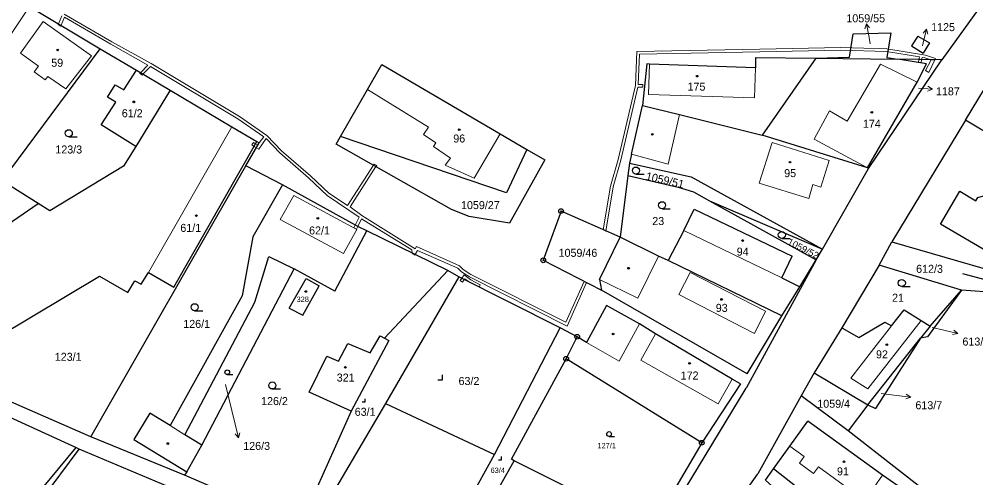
# Model space of a CAD drawing. Extents: x -694609 to -690140, y -1033292 to -1029794.
# Drawn here: x -692506.4 to -692303.2, y -1031568.1 to -1031470.7 of the extents above; entities that cross this region are included whole.
import ezdxf
from ezdxf.enums import TextEntityAlignment as Align

# ---------------------------------------------------------------- set-up
doc = ezdxf.new("R2010")
doc.units = 0
doc.header["$LTSCALE"] = 0.68
for name, color, linetype, lineweight in [('1', 7, 'Continuous', 25), ('13', 7, 'Continuous', 13), ('3', 7, 'Continuous', 25), ('4', 7, 'Continuous', 13), ('5', 7, 'Continuous', 25), ('7', 7, 'Continuous', 13), ('8', 7, 'Continuous', 25)]:
    doc.layers.add(name, color=color, linetype=linetype, lineweight=lineweight)
doc.layers.add('2', color=7, linetype='Continuous')

msp = doc.modelspace()

# ---------------------------------------------------------------- linework, layer by layer
at = {"layer": '1'}
for p, q in [((-692296.63, -1031460.11), (-692310.42, -1031479.32)), ((-692504.17, -1031467.97), (-692489.17, -1031476.96)), ((-692330.05, -1031478.76), (-692329.26, -1031473.82)), ((-692329.26, -1031473.82), (-692321.23, -1031473.6)), ((-692321.23, -1031473.6), (-692322.07, -1031478.82)), ((-692315.53, -1031474.28), (-692316.87, -1031476.38)), ((-692315.53, -1031474.28), (-692313.04, -1031475.74)), ((-692305.4, -1031492.16), (-692294.9, -1031474.76)), ((-692509.98, -1031505.02), (-692489.17, -1031476.96)), ((-692489.17, -1031476.96), (-692481.44, -1031481.54)), ((-692316.87, -1031476.38), (-692314.35, -1031477.91)), ((-692313.04, -1031475.74), (-692314.35, -1031477.91)), ((-692349.96, -1031478.82), (-692349.98, -1031481.02)), ((-692337.17, -1031478.95), (-692330.05, -1031478.76)), ((-692337.17, -1031478.95), (-692319.74, -1031479.19)), ((-692322.07, -1031478.82), (-692319.74, -1031479.19)), ((-692310.42, -1031479.32), (-692319.74, -1031479.19)), ((-692313.7, -1031480.16), (-692319.74, -1031479.19)), ((-692432.37, -1031485.64), (-692429.33, -1031480.34)), ((-692429.33, -1031480.34), (-692404.21, -1031495.03)), ((-692373.05, -1031480.2), (-692374, -1031489.01)), ((-692372.47, -1031480.22), (-692373.05, -1031480.2)), ((-692349.98, -1031481.02), (-692372.47, -1031480.22)), ((-692325.97, -1031502.39), (-692310.42, -1031479.32)), ((-692484.12, -1031485.72), (-692481.44, -1031481.54)), ((-692481.44, -1031481.54), (-692474.29, -1031485.77)), ((-692487.59, -1031487.25), (-692485.93, -1031484.64)), ((-692485.93, -1031484.64), (-692484.12, -1031485.72)), ((-692485.8, -1031488.33), (-692487.59, -1031487.25)), ((-692474.29, -1031485.77), (-692481.58, -1031497.74)), ((-692474.29, -1031485.77), (-692461.2, -1031493.52)), ((-692438.08, -1031495.6), (-692432.37, -1031485.64)), ((-692488.9, -1031493.15), (-692485.8, -1031488.33)), ((-692376.3, -1031499.39), (-692374, -1031489.01)), ((-692374, -1031489.01), (-692366.1, -1031490.96)), ((-692366.1, -1031490.96), (-692348.54, -1031495.3)), ((-692481.58, -1031497.74), (-692488.9, -1031493.15)), ((-692305.4, -1031492.16), (-692321.02, -1031518)), ((-692243.47, -1031529.16), (-692305.4, -1031492.16)), ((-692461.2, -1031493.52), (-692455.86, -1031496.68)), ((-692404.21, -1031495.03), (-692398.52, -1031498.35)), ((-692326.22, -1031502.28), (-692348.54, -1031495.3)), ((-692473.53, -1031527.58), (-692455.86, -1031496.68)), ((-692458.24, -1031501.84), (-692455.37, -1031496.97)), ((-692455.86, -1031496.68), (-692455.37, -1031496.97)), ((-692439.01, -1031497.22), (-692438.08, -1031495.6)), ((-692414.51, -1031511.12), (-692439.01, -1031497.22)), ((-692402.85, -1031507.59), (-692438.08, -1031495.6)), ((-692481.58, -1031497.74), (-692484.21, -1031501.91)), ((-692398.52, -1031498.35), (-692402.85, -1031507.59)), ((-692398.52, -1031498.35), (-692394.71, -1031500.58)), ((-692376.3, -1031499.39), (-692376.72, -1031501.27)), ((-692394.71, -1031500.58), (-692402.2, -1031514.03)), ((-692376.72, -1031501.27), (-692377.08, -1031503.89)), ((-692376.72, -1031501.27), (-692363.67, -1031504.14)), ((-692484.21, -1031501.91), (-692499.85, -1031511.41)), ((-692491.14, -1031559.38), (-692458.24, -1031501.84)), ((-692450.42, -1031505.9), (-692458.24, -1031501.84)), ((-692335.75, -1031519.57), (-692325.97, -1031502.39)), ((-692325.97, -1031502.39), (-692326.22, -1031502.28)), ((-692502.29, -1031509.87), (-692509.98, -1031505.02)), ((-692377.08, -1031503.89), (-692378.73, -1031517.02)), ((-692377.08, -1031503.89), (-692366.42, -1031506.38)), ((-692363.67, -1031504.14), (-692335.75, -1031519.57)), ((-692450.42, -1031505.9), (-692456.71, -1031516.92)), ((-692434.32, -1031514.78), (-692450.42, -1031505.9)), ((-692366.42, -1031506.38), (-692363.18, -1031507.35)), ((-692363.18, -1031507.35), (-692359.74, -1031509.25)), ((-692359.74, -1031509.25), (-692337.1, -1031521.78)), ((-692359.74, -1031509.25), (-692335.75, -1031519.57)), ((-692524.76, -1031525.17), (-692502.29, -1031509.87)), ((-692499.85, -1031511.41), (-692502.29, -1031509.87)), ((-692410.81, -1031512.61), (-692414.51, -1031511.12)), ((-692391.28, -1031511.44), (-692395.05, -1031521.91)), ((-692378.73, -1031517.02), (-692391.28, -1031511.44)), ((-692365.23, -1031515.6), (-692362.98, -1031511.04)), ((-692362.98, -1031511.04), (-692342.21, -1031521.04)), ((-692402.2, -1031514.03), (-692410.81, -1031512.61)), ((-692439.34, -1031528.46), (-692432.49, -1031515.67)), ((-692432.49, -1031515.67), (-692434.32, -1031514.78)), ((-692415.31, -1031524.07), (-692432.49, -1031515.67)), ((-692365.23, -1031515.6), (-692368.55, -1031521.98)), ((-692456.71, -1031516.92), (-692459.01, -1031529.42)), ((-692383.11, -1031525.99), (-692378.73, -1031517.02)), ((-692370.56, -1031521.01), (-692378.73, -1031517.02)), ((-692337.1, -1031521.78), (-692335.75, -1031519.57)), ((-692323.7, -1031522.94), (-692321.02, -1031518)), ((-692321.02, -1031518), (-692283.17, -1031528.96)), ((-692456.3, -1031530.77), (-692453.3, -1031521.07)), ((-692453.3, -1031521.07), (-692447.98, -1031523.75)), ((-692368.55, -1031521.98), (-692370.56, -1031521.01)), ((-692337.1, -1031521.78), (-692351.95, -1031549.08)), ((-692344.42, -1031525.61), (-692342.21, -1031521.04)), ((-692340.58, -1031527.51), (-692337.1, -1031521.78)), ((-692467.54, -1031561.2), (-692447.98, -1031523.75)), ((-692439.34, -1031528.46), (-692447.98, -1031523.75)), ((-692395.05, -1031521.91), (-692382.67, -1031528.28)), ((-692344.36, -1031533.72), (-692368.55, -1031521.98)), ((-692323.7, -1031522.94), (-692331.63, -1031536.26)), ((-692306.24, -1031528.23), (-692323.7, -1031522.94)), ((-692514.18, -1031540.14), (-692489.29, -1031525.3)), ((-692489.29, -1031525.3), (-692483.26, -1031528.76)), ((-692480.41, -1031526.97), (-692478.91, -1031524.51)), ((-692478.91, -1031524.51), (-692473.53, -1031527.58)), ((-692449.04, -1031532.09), (-692445.42, -1031525.77)), ((-692445.42, -1031525.77), (-692442.63, -1031527.34)), ((-692415.31, -1031524.07), (-692428.77, -1031538.44)), ((-692412.99, -1031525.42), (-692428.58, -1031552.29)), ((-692412.99, -1031525.42), (-692415.31, -1031524.07)), ((-692391.46, -1031536.28), (-692412.99, -1031525.42)), ((-692344.42, -1031525.61), (-692340.58, -1031527.51)), ((-692483.26, -1031528.76), (-692481.81, -1031526.3)), ((-692481.81, -1031526.3), (-692480.41, -1031526.97)), ((-692446.13, -1031533.59), (-692442.63, -1031527.34)), ((-692383.11, -1031525.99), (-692382.67, -1031528.28)), ((-692344.36, -1031533.72), (-692340.58, -1031527.51)), ((-692459.01, -1031529.42), (-692474.29, -1031557.03)), ((-692351.78, -1031546.03), (-692382.67, -1031528.28)), ((-692306.24, -1031528.23), (-692313.46, -1031538.18)), ((-692312.88, -1031535.92), (-692306.24, -1031528.23)), ((-692291.29, -1031529.36), (-692306.24, -1031528.23)), ((-692471.2, -1031558.98), (-692456.3, -1031530.77)), ((-692381.62, -1031531.49), (-692385.85, -1031539.38)), ((-692374.59, -1031535.38), (-692381.62, -1031531.49)), ((-692449.04, -1031532.09), (-692446.13, -1031533.59)), ((-692351.78, -1031546.03), (-692344.36, -1031533.72)), ((-692371.22, -1031537.52), (-692374.59, -1031535.38)), ((-692328.01, -1031538.32), (-692322.51, -1031535.08)), ((-692322.51, -1031535.08), (-692321.07, -1031535.82)), ((-692312.88, -1031535.92), (-692314.92, -1031538.42)), ((-692314.79, -1031534.7), (-692312.88, -1031535.92)), ((-692431.8, -1031541.58), (-692429.69, -1031537.95)), ((-692429.69, -1031537.95), (-692428.77, -1031538.44)), ((-692405.41, -1031563.18), (-692391.46, -1031536.28)), ((-692387.85, -1031538.15), (-692391.46, -1031536.28)), ((-692354.92, -1031547.12), (-692371.22, -1031537.52)), ((-692331.63, -1031536.26), (-692337.56, -1031545.79)), ((-692331.63, -1031536.26), (-692328.01, -1031538.32)), ((-692438.52, -1031543.34), (-692436.55, -1031539.59)), ((-692436.55, -1031539.59), (-692431.8, -1031541.58)), ((-692427.84, -1031538.96), (-692435.86, -1031553.94)), ((-692428.77, -1031538.44), (-692427.84, -1031538.96)), ((-692390.19, -1031542.82), (-692387.85, -1031538.15)), ((-692385.85, -1031539.38), (-692387.85, -1031538.15)), ((-692326.16, -1031552.6), (-692314.92, -1031538.42)), ((-692314.92, -1031538.42), (-692324.53, -1031553.4)), ((-692313.46, -1031538.18), (-692314.92, -1031538.42)), ((-692444.75, -1031549.9), (-692441, -1031542.3)), ((-692441, -1031542.3), (-692438.52, -1031543.34)), ((-692401.81, -1031564.18), (-692390.19, -1031542.82)), ((-692361.4, -1031560.66), (-692390.19, -1031542.82)), ((-692337.56, -1031545.79), (-692340.29, -1031550.69)), ((-692337.56, -1031545.79), (-692326.16, -1031552.6)), ((-692353.15, -1031548.17), (-692361.4, -1031560.66)), ((-692353.15, -1031548.17), (-692354.92, -1031547.12)), ((-692435.86, -1031553.94), (-692444.75, -1031549.9)), ((-692378.81, -1031593.37), (-692351.95, -1031549.08)), ((-692491.61, -1031559.19), (-692510.92, -1031550.77)), ((-692428.58, -1031552.29), (-692444.25, -1031578.99)), ((-692428.58, -1031552.29), (-692405.41, -1031563.18)), ((-692340.29, -1031550.69), (-692349.51, -1031567.24)), ((-692330.34, -1031558.16), (-692340.29, -1031550.69)), ((-692514.5, -1031552.43), (-692494.27, -1031561.65)), ((-692435.86, -1031553.94), (-692446.6, -1031578.05)), ((-692326.16, -1031552.6), (-692330.34, -1031558.16)), ((-692326.16, -1031552.6), (-692324.53, -1031553.4)), ((-692478.57, -1031554.41), (-692482.03, -1031559.95)), ((-692474.29, -1031557.03), (-692478.57, -1031554.41)), ((-692342.69, -1031561.4), (-692338.84, -1031556.07)), ((-692323.02, -1031567.51), (-692338.84, -1031556.07)), ((-692273.27, -1031602.4), (-692330.34, -1031558.16)), ((-692491.14, -1031559.38), (-692491.61, -1031559.19)), ((-692471.27, -1031567.56), (-692491.14, -1031559.38)), ((-692482.03, -1031559.95), (-692470.74, -1031566.87)), ((-692467.54, -1031561.2), (-692471.2, -1031558.98)), ((-692546.37, -1031624.62), (-692494.27, -1031561.65)), ((-692542.42, -1031627.11), (-692493.57, -1031562)), ((-692494.27, -1031561.65), (-692493.57, -1031562)), ((-692455.1, -1031578.2), (-692493.57, -1031562)), ((-692470.74, -1031566.87), (-692467.54, -1031561.2)), ((-692346.14, -1031566.21), (-692342.69, -1031561.4)), ((-692420.15, -1031589.65), (-692405.41, -1031563.18)), ((-692406.71, -1031574.21), (-692401.26, -1031564.53)), ((-692401.26, -1031564.53), (-692401.81, -1031564.18)), ((-692324.02, -1031583.53), (-692346.14, -1031566.21)), ((-692470.74, -1031566.87), (-692471.27, -1031567.56)), ((-692446.6, -1031578.05), (-692471.27, -1031567.56)), ((-692370.79, -1031597.28), (-692349.51, -1031567.24)), ((-692318.1, -1031570.94), (-692323.02, -1031567.51))]:
    msp.add_line(p, q, dxfattribs=at)
for points in [[(-692349.96, -1031478.82), (-692337.17, -1031478.95), (-692348.54, -1031495.3)], [(-692326.22, -1031502.28), (-692315.68, -1031484.08), (-692313.7, -1031480.16)], [(-692321.07, -1031535.82), (-692318.38, -1031532.45), (-692314.79, -1031534.7)], [(-692361.4, -1031560.66), (-692372.16, -1031579.03), (-692401.26, -1031564.53)], [(-692345.68, -1031570.59), (-692347.88, -1031568.63), (-692346.14, -1031566.21)]]:
    msp.add_lwpolyline(points, dxfattribs=at)
msp.add_lwpolyline([(-692306.6, -1031507.25), (-692303.23, -1031509.25), (-692302.79, -1031508.59), (-692300.57, -1031507.94), (-692299.93, -1031508.31), (-692296.03, -1031501.86), (-692287.74, -1031506.77), (-692291.49, -1031512.97), (-692293.3, -1031511.9), (-692295.89, -1031516.29), (-692296.67, -1031515.84), (-692299.56, -1031520.75), (-692310.71, -1031514.2)], close=True, dxfattribs=at)
at = {"layer": '13'}
for points in [[(-692497.26, -1031469.98), (-692497.98, -1031471.68), (-692497.46, -1031471.99), (-692496.73, -1031470.27), (-692486.91, -1031475.97), (-692478.99, -1031480.42), (-692480.58, -1031482.05), (-692480.07, -1031482.35), (-692478.46, -1031480.74), (-692459.9, -1031491.83), (-692454.38, -1031495.68), (-692455.37, -1031496.97), (-692455.67, -1031497.48), (-692455.98, -1031498), (-692455.47, -1031498.32), (-692453.88, -1031496.02), (-692451.02, -1031499.11), (-692444.91, -1031504.39), (-692440.96, -1031508.11), (-692434.12, -1031512.76), (-692434.97, -1031514.42), (-692434.44, -1031514.71), (-692433.62, -1031513.1), (-692422.94, -1031519.71), (-692422.86, -1031520.38), (-692422.23, -1031520.69), (-692421.75, -1031519.83), (-692413.21, -1031523.55), (-692412.43, -1031524.33), (-692410.71, -1031525.43), (-692389.96, -1031535.86), (-692385.84, -1031526.65), (-692386.37, -1031526.38), (-692390.26, -1031535.04), (-692410.41, -1031524.91), (-692412.05, -1031523.87), (-692412.83, -1031523.07), (-692421.96, -1031518.99), (-692422.22, -1031519.45), (-692433.57, -1031512.41), (-692436.09, -1031510.58)], [(-692436.09, -1031510.58), (-692430.58, -1031502), (-692431.11, -1031501.7), (-692436.59, -1031510.26), (-692440.58, -1031507.64), (-692444.5, -1031503.95), (-692450.61, -1031498.68), (-692453.76, -1031495.37), (-692459.57, -1031491.33), (-692478.35, -1031480.11), (-692486.69, -1031475.49), (-692496.79, -1031469.62)]]:
    msp.add_lwpolyline(points, dxfattribs=at)
for points in [[(-692497.98, -1031471.68), (-692498.07, -1031471.88), (-692497.54, -1031472.18), (-692497.46, -1031471.99)], [(-692331.84, -1031476.67), (-692349.06, -1031477.05), (-692375.18, -1031477.56), (-692375.48, -1031484.79), (-692379.18, -1031500.48), (-692380.78, -1031506.13), (-692382.3, -1031515.43), (-692381.74, -1031515.68), (-692380.2, -1031506.27), (-692378.6, -1031500.64), (-692374.94, -1031485.13), (-692373.88, -1031485.14), (-692373.88, -1031484.54), (-692374.87, -1031484.53), (-692374.6, -1031478.14), (-692349.04, -1031477.65), (-692331.84, -1031477.27), (-692322.15, -1031477.55), (-692315.19, -1031478.69), (-692315.29, -1031479.25), (-692314.7, -1031479.26), (-692314.6, -1031478.8), (-692314, -1031478.9), (-692312.69, -1031479.29), (-692311.89, -1031479.3), (-692311.75, -1031479.02), (-692313.86, -1031478.32), (-692322.09, -1031476.95)], [(-692315.29, -1031479.25), (-692315.4, -1031479.87), (-692314.84, -1031479.96), (-692314.7, -1031479.26)], [(-692312.69, -1031479.29), (-692313.89, -1031481.59), (-692313.17, -1031481.99), (-692311.89, -1031479.3)], [(-692480.58, -1031482.05), (-692480.7, -1031482.23), (-692480.19, -1031482.55), (-692480.07, -1031482.35)], [(-692456.59, -1031496.9), (-692456.91, -1031497.41), (-692456.45, -1031497.71), (-692455.98, -1031498), (-692455.67, -1031497.48), (-692456.15, -1031497.18)], [(-692431.11, -1031501.7), (-692430.58, -1031502), (-692430.42, -1031501.75), (-692430.95, -1031501.45)], [(-692434.97, -1031514.42), (-692435.27, -1031515), (-692434.74, -1031515.29), (-692434.44, -1031514.71)], [(-692422.86, -1031520.38), (-692422.84, -1031520.54), (-692422.32, -1031520.83), (-692422.23, -1031520.69)], [(-692412.37, -1031525.73), (-692412.7, -1031526.19), (-692412.22, -1031526.55), (-692411.82, -1031526.01)], [(-692408.68, -1031527.59), (-692408.42, -1031527.09), (-692410.44, -1031526.05), (-692411.83, -1031525.02), (-692412.37, -1031525.73), (-692411.82, -1031526.01), (-692411.71, -1031525.86), (-692410.75, -1031526.55)]]:
    msp.add_lwpolyline(points, close=True, dxfattribs=at)
at = {"layer": '3'}
for p, q in [((-692495.813, -1031495.66), (-692494.063, -1031495.66)), ((-692375.373, -1031503.59), (-692373.623, -1031503.59)), ((-692369.823, -1031510.96), (-692368.073, -1031510.96)), ((-692344.393, -1031517.27), (-692342.643, -1031517.27)), ((-692318.913, -1031527.48), (-692317.163, -1031527.48)), ((-692469.083, -1031532.62), (-692467.333, -1031532.62)), ((-692462.155, -1031546.19), (-692460.983, -1031546.19)), ((-692452.593, -1031549.24), (-692450.843, -1031549.24)), ((-692381.065, -1031559.31), (-692379.893, -1031559.31))]:
    msp.add_line(p, q, dxfattribs=at)
for points in [[(-692306.013, -1031524.726), (-692300.218, -1031526.279), (-692301.032, -1031525.542)], [(-692417.421, -1031547.26), (-692416.42, -1031547.26), (-692416.42, -1031546.26)], [(-692433.541, -1031551.99), (-692432.87, -1031551.99), (-692432.87, -1031551.32)], [(-692404.591, -1031564.26), (-692403.92, -1031564.26), (-692403.92, -1031563.59)]]:
    msp.add_lwpolyline(points, dxfattribs=at)
for centre, radius in [((-692495.8129, -1031494.9098), 0.75), ((-692375.3729, -1031502.8398), 0.75), ((-692369.8229, -1031510.2098), 0.75), ((-692344.3929, -1031516.5198), 0.75), ((-692318.9129, -1031526.7298), 0.75), ((-692469.0829, -1031531.8698), 0.75), ((-692462.1552, -1031545.6874), 0.5025), ((-692452.5929, -1031548.4898), 0.75), ((-692381.0652, -1031558.8074), 0.5025)]:
    msp.add_circle(centre, radius, dxfattribs=at)
at = {"layer": '4'}
for p, q in [((-692501.23, -1031471.17), (-692506.08, -1031477.91)), ((-692501.23, -1031471.17), (-692490.98, -1031478.46)), ((-692502.26, -1031480.65), (-692506.08, -1031477.91)), ((-692496.43, -1031485.5), (-692490.98, -1031478.46)), ((-692503.14, -1031481.87), (-692502.26, -1031480.65)), ((-692372.47, -1031480.22), (-692372.7, -1031486.66)), ((-692323.44, -1031480.27), (-692330.52, -1031492.35)), ((-692323.44, -1031480.27), (-692315.68, -1031484.08)), ((-692500.79, -1031483.57), (-692503.14, -1031481.87)), ((-692500.26, -1031482.83), (-692500.79, -1031483.57)), ((-692496.43, -1031485.5), (-692500.26, -1031482.83)), ((-692432.37, -1031485.64), (-692419.42, -1031493.64)), ((-692366.1, -1031490.96), (-692368.54, -1031501.46)), ((-692478.91, -1031524.51), (-692461.2, -1031493.52)), ((-692420.51, -1031495.16), (-692419.42, -1031493.64)), ((-692417.86, -1031496.98), (-692420.51, -1031495.16)), ((-692404.21, -1031495.03), (-692409.76, -1031504.49)), ((-692418.39, -1031497.76), (-692417.86, -1031496.98)), ((-692346.48, -1031496.87), (-692349.19, -1031505.52)), ((-692346.48, -1031496.87), (-692334.31, -1031500.67)), ((-692337.54, -1031496.19), (-692326.22, -1031502.28)), ((-692414.77, -1031500.24), (-692418.39, -1031497.76)), ((-692376.3, -1031499.39), (-692368.54, -1031501.46)), ((-692415.89, -1031501.73), (-692414.77, -1031500.24)), ((-692334.31, -1031500.67), (-692336.08, -1031506.34)), ((-692415.89, -1031501.73), (-692409.76, -1031504.49)), ((-692338.69, -1031508.8), (-692349.19, -1031505.52)), ((-692337.79, -1031505.79), (-692338.69, -1031508.8)), ((-692336.08, -1031506.34), (-692337.79, -1031505.79)), ((-692448.03, -1031508.14), (-692450.93, -1031513.22)), ((-692434.64, -1031515.34), (-692448.03, -1031508.14)), ((-692437.49, -1031520.46), (-692450.93, -1031513.22)), ((-692434.64, -1031515.34), (-692437.49, -1031520.46)), ((-692365.23, -1031515.6), (-692344.42, -1031525.61)), ((-692374.94, -1031529.98), (-692370.56, -1031521.01)), ((-692366.28, -1031529.19), (-692363.87, -1031524.5)), ((-692347.85, -1031532.73), (-692363.87, -1031524.5)), ((-692374.94, -1031529.98), (-692383.11, -1031525.99)), ((-692350.18, -1031537.44), (-692366.28, -1031529.19)), ((-692347.85, -1031532.73), (-692350.18, -1031537.44)), ((-692374.59, -1031535.38), (-692378.91, -1031543.36)), ((-692326.15, -1031549.21), (-692314.79, -1031534.7)), ((-692325.36, -1031541.31), (-692321.07, -1031535.82)), ((-692371.22, -1031537.52), (-692374.31, -1031543.09)), ((-692385.85, -1031539.38), (-692378.91, -1031543.36)), ((-692329.75, -1031546.95), (-692325.36, -1031541.31)), ((-692329.75, -1031546.95), (-692326.15, -1031549.21)), ((-692471.2, -1031558.98), (-692474.29, -1031557.03)), ((-692342.69, -1031561.4), (-692339.64, -1031563.6)), ((-692339.64, -1031563.6), (-692340.67, -1031565.02)), ((-692340.67, -1031565.02), (-692337.66, -1031567.21)), ((-692337.66, -1031567.21), (-692336.63, -1031565.78)), ((-692336.63, -1031565.78), (-692326.78, -1031572.9)), ((-692326.78, -1031572.9), (-692323.02, -1031567.51))]:
    msp.add_line(p, q, dxfattribs=at)
for points in [[(-692504.17, -1031467.97), (-692512.31, -1031480.07), (-692517.3, -1031476.74)], [(-692372.7, -1031486.66), (-692350.22, -1031487.42), (-692349.98, -1031481.02)], [(-692330.52, -1031492.35), (-692334.3, -1031490.16), (-692337.54, -1031496.19)], [(-692374.31, -1031543.09), (-692357.93, -1031552.41), (-692354.92, -1031547.12)]]:
    msp.add_lwpolyline(points, dxfattribs=at)
at = {"layer": '5'}
for centre in [(-692498.1668, -1031477.2292), (-692362.3668, -1031482.7892), (-692482.0068, -1031488.2592), (-692325.2868, -1031490.4592), (-692412.9068, -1031494.1592), (-692371.9068, -1031495.1592), (-692342.6668, -1031501.0592), (-692468.7168, -1031512.4092), (-692442.9268, -1031512.9892), (-692352.7268, -1031517.7092), (-692376.9468, -1031523.5792), (-692445.4768, -1031528.5292), (-692357.1968, -1031530.2192), (-692380.2268, -1031537.5692), (-692322.0968, -1031539.8092), (-692363.9868, -1031543.7992), (-692437.0668, -1031544.6492), (-692474.7768, -1031560.8292), (-692331.2068, -1031564.6992)]:
    msp.add_circle(centre, 0.175, dxfattribs=at)
at = {"layer": '7'}
for p, q in [((-692326.433, -1031471.654), (-692326.733, -1031472.733)), ((-692313.675, -1031472.796), (-692314.388, -1031473.659)), ((-692312.406, -1031485.519), (-692313.37, -1031484.95)), ((-692307.036, -1031537.425), (-692307.899, -1031536.712)), ((-692317.031, -1031550.966), (-692317.964, -1031550.347)), ((-692459.744, -1031559.622), (-692459.5, -1031558.529))]:
    msp.add_line(p, q, dxfattribs=at)
for points in [[(-692325.6, -1031475.89), (-692325.86, -1031474.6), (-692326.433, -1031471.654), (-692325.75, -1031472.542)], [(-692314.5, -1031476.36), (-692314.35, -1031475.72), (-692313.675, -1031472.796), (-692313.412, -1031473.884)], [(-692315.4, -1031485.31), (-692312.406, -1031485.519), (-692313.44, -1031485.949)], [(-692312.48, -1031536.15), (-692309.96, -1031536.75), (-692307.036, -1031537.425), (-692308.124, -1031537.688)], [(-692462.53, -1031548.31), (-692460.47, -1031556.71), (-692459.744, -1031559.622), (-692460.472, -1031558.771)], [(-692323.32, -1031550.18), (-692320.01, -1031550.6), (-692317.031, -1031550.966), (-692318.086, -1031551.341)]]:
    msp.add_lwpolyline(points, dxfattribs=at)
at = {"layer": '8'}
for centre, radius in [((-692391.28, -1031511.4399), 0.5), ((-692391.28, -1031511.4399), 0.0303), ((-692395.05, -1031521.9099), 0.5), ((-692395.05, -1031521.9099), 0.0303), ((-692387.85, -1031538.1499), 0.5), ((-692387.85, -1031538.1499), 0.0303), ((-692390.19, -1031542.8199), 0.5), ((-692390.19, -1031542.8199), 0.0303), ((-692361.4, -1031560.6599), 0.5), ((-692361.4, -1031560.6599), 0.0303)]:
    msp.add_circle(centre, radius, dxfattribs=at)

# ---------------------------------------------------------------- texts
at = {"layer": '2'}
for s, height, p in [('1059/55', 1.7, (-692326.579, -1031471.345)), ('59', 1.7, (-692498.269, -1031480.795)), ('175', 1.7, (-692362.519, -1031485.865)), ('61/2', 1.7, (-692482.339, -1031491.515)), ('174', 1.7, (-692325.279, -1031493.745)), ('96', 1.7, (-692412.899, -1031496.885)), ('123/3', 1.7, (-692495.82, -1031499.215)), ('95', 1.7, (-692342.629, -1031504.235)), ('1059/27', 1.7, (-692408.409, -1031511.035)), ('23', 1.7, (-692370.639, -1031514.415)), ('61/1', 1.7, (-692469.909, -1031515.865)), ('62/1', 1.7, (-692442.569, -1031516.415)), ('1059/46', 1.7, (-692387.689, -1031521.162)), ('94', 1.7, (-692352.709, -1031520.915)), ('612/3', 1.7, (-692313.03, -1031524.565)), ('328', 1.14, (-692446.13, -1031530.755)), ('21', 1.7, (-692319.719, -1031530.705)), ('93', 1.7, (-692357.159, -1031532.855)), ('126/1', 1.7, (-692468.65, -1031536.265)), ('123/1', 1.7, (-692495.94, -1031543.255)), ('92', 1.7, (-692323.129, -1031542.735)), ('321', 1.7, (-692437.009, -1031547.665)), ('172', 1.7, (-692363.979, -1031547.225)), ('63/2', 1.7, (-692410.829, -1031548.395)), ('126/2', 1.7, (-692452.13, -1031552.665)), ('1059/4', 1.7, (-692333.38, -1031553.225)), ('63/1', 1.7, (-692432.879, -1031554.935)), ('127/1', 1.14, (-692381.589, -1031561.845)), ('63/4', 1.14, (-692404.72, -1031567.085)), ('91', 1.7, (-692331.419, -1031567.585))]:
    msp.add_text(s, height=height, dxfattribs=at).set_placement(p, align=Align.CENTER)
for s, p in [('1125', (-692312.68, -1031473.225)), ('1187', (-692311.66, -1031486.862)), ('613/8', (-692306.04, -1031540.015)), ('613/7', (-692316.03, -1031553.545)), ('126/3', (-692458.76, -1031562.185))]:
    msp.add_text(s, height=1.7, dxfattribs=at).set_placement(p)
msp.add_text('1059/51', height=1.7, rotation=347, dxfattribs=at).set_placement((-692369.3882, -1031505.706), align=Align.CENTER)
at = {"layer": '2', "width": 1.05}
msp.add_text('1059/52', height=1.4, rotation=333, dxfattribs=at).set_placement((-692340.1563, -1031520.044), align=Align.CENTER)

doc.saveas('drawing.dxf')
